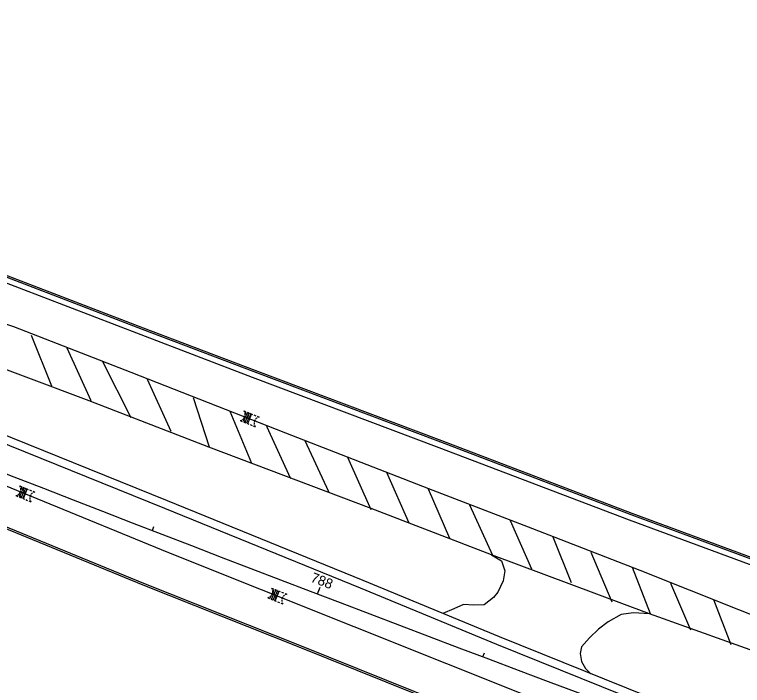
# Model space of a CAD drawing. Extents: x 2349621 to 2352073, y 625611 to 626553.
# Drawn here: x 2351167.3 to 2351373.1, y 625866.1 to 626055.7 of the extents above; entities that cross this region are included whole.
import ezdxf

# ---------------------------------------------------------------- set-up
doc = ezdxf.new("R2010")
doc.units = 0
for name, color, linetype in [('PM_X_Cells', 7, 'Continuous'), ('PM_X_Edge_Line', 7, 'Continuous'), ('PM_X_Lane_Line', 7, 'Continuous'), ('PV_X_Curb', 7, 'Continuous'), ('PV_X_EOP', 7, 'Continuous'), ('RW_X_CL', 7, 'Continuous'), ('RW_X_CL_100_Stations', 7, 'Continuous'), ('RW_X_CL_500_Stations', 7, 'Continuous')]:
    doc.layers.add(name, color=color, linetype=linetype)

msp = doc.modelspace()

# ---------------------------------------------------------------- linework, layer by layer
at = {"layer": 'PM_X_Cells'}
for p, q in [((2351232.19, 625943.66), (2351232.75, 625943.44)), ((2351233.62, 625941.02), (2351232.56, 625943.51)), ((2351233.13, 625943.29), (2351233.68, 625943.06)), ((2351233.87, 625941.65), (2351233.19, 625943.26)), ((2351233.24, 625940.08), (2351234.34, 625942.79)), ((2351234.13, 625942.28), (2351233.82, 625943)), ((2351234.06, 625942.91), (2351234.61, 625942.68)), ((2351231.09, 625940.95), (2351231.65, 625940.72)), ((2351231.66, 625940.72), (2351231.51, 625941.08)), ((2351232.29, 625940.46), (2351231.92, 625941.34)), ((2351232.92, 625940.21), (2351232.27, 625941.75)), ((2351233.36, 625940.39), (2351232.51, 625942.41)), ((2351233.79, 625941.44), (2351233.79, 625941.44)), ((2351234.99, 625942.53), (2351235.55, 625942.3)), ((2351235.92, 625942.15), (2351236.48, 625941.93)), ((2351232.02, 625940.57), (2351232.58, 625940.34)), ((2351232.96, 625940.19), (2351233.51, 625939.97)), ((2351233.89, 625939.81), (2351234.45, 625939.59)), ((2351234.82, 625939.44), (2351235.38, 625939.21)), ((2351168.78, 625922.47), (2351169.34, 625922.25)), ((2351170.2, 625919.83), (2351169.15, 625922.32)), ((2351169.71, 625922.09), (2351170.27, 625921.87)), ((2351170.46, 625920.46), (2351169.78, 625922.07)), ((2351168.88, 625919.27), (2351168.51, 625920.15)), ((2351169.5, 625919.02), (2351168.85, 625920.55)), ((2351169.95, 625919.2), (2351169.09, 625921.22)), ((2351169.82, 625918.89), (2351170.92, 625921.6)), ((2351170.37, 625920.24), (2351170.37, 625920.24)), ((2351170.71, 625921.09), (2351170.41, 625921.81)), ((2351170.64, 625921.72), (2351171.2, 625921.49)), ((2351171.58, 625921.34), (2351172.13, 625921.11)), ((2351172.51, 625920.96), (2351173.06, 625920.73)), ((2351167.68, 625919.76), (2351168.23, 625919.53)), ((2351168.25, 625919.53), (2351168.09, 625919.89)), ((2351168.61, 625919.38), (2351169.17, 625919.15)), ((2351169.54, 625919), (2351170.1, 625918.77)), ((2351170.48, 625918.62), (2351171.03, 625918.4)), ((2351171.41, 625918.24), (2351171.96, 625918.02)), ((2351239.98, 625893.59), (2351240.53, 625893.37)), ((2351241.4, 625890.95), (2351240.35, 625893.44)), ((2351240.08, 625890.39), (2351239.7, 625891.27)), ((2351240.7, 625890.14), (2351240.05, 625891.68)), ((2351241.15, 625890.32), (2351240.29, 625892.34)), ((2351240.91, 625893.21), (2351241.47, 625892.99)), ((2351241.66, 625891.58), (2351240.98, 625893.19)), ((2351241.02, 625890.01), (2351242.12, 625892.72)), ((2351241.57, 625891.37), (2351241.57, 625891.37)), ((2351241.91, 625892.21), (2351241.6, 625892.93)), ((2351241.84, 625892.84), (2351242.4, 625892.61)), ((2351242.78, 625892.46), (2351243.33, 625892.23)), ((2351243.71, 625892.08), (2351244.26, 625891.85)), ((2351238.88, 625890.88), (2351239.43, 625890.65)), ((2351239.44, 625890.65), (2351239.29, 625891.01)), ((2351239.81, 625890.5), (2351240.37, 625890.27)), ((2351240.74, 625890.12), (2351241.3, 625889.9)), ((2351241.67, 625889.74), (2351242.23, 625889.52)), ((2351242.61, 625889.37), (2351243.16, 625889.14))]:
    msp.add_line(p, q, dxfattribs=at)
for centre, start, end in [((2351230.8, 625942.65), 20.0075, 35.9489), ((2351230.8, 625942.65), 356.8106, 12.7435), ((2351230.8, 625942.65), 279.8966, 295.8433), ((2351230.8, 625942.65), 303.101, 319.0339), ((2351230.8, 625942.65), 326.3132, 349.543), ((2351236.78, 625940.22), 146.3043, 169.5319), ((2351236.78, 625940.22), 123.101, 139.0326), ((2351236.78, 625940.22), 99.8966, 115.8391), ((2351236.78, 625940.22), 176.81, 192.7435), ((2351236.78, 625940.22), 200.0045, 215.9489), ((2351167.38, 625921.46), 20.0075, 35.9489), ((2351167.38, 625921.46), 303.101, 319.0339), ((2351167.38, 625921.46), 326.3132, 349.543), ((2351167.38, 625921.46), 356.8106, 12.7435), ((2351173.36, 625919.03), 123.101, 139.0326), ((2351173.36, 625919.03), 99.8966, 115.8391), ((2351167.38, 625921.46), 279.8966, 295.8433), ((2351173.36, 625919.03), 176.81, 192.7435), ((2351173.36, 625919.03), 146.3043, 169.5319), ((2351173.36, 625919.03), 200.0045, 215.9489), ((2351238.58, 625892.58), 20.0075, 35.9489), ((2351238.58, 625892.58), 303.101, 319.0339), ((2351238.58, 625892.58), 326.3132, 349.543), ((2351238.58, 625892.58), 356.8106, 12.7435), ((2351244.56, 625890.15), 123.101, 139.0326), ((2351244.56, 625890.15), 99.8966, 115.8391), ((2351238.58, 625892.58), 279.8966, 295.8433), ((2351244.56, 625890.15), 176.81, 192.7435), ((2351244.56, 625890.15), 146.3043, 169.5319), ((2351244.56, 625890.15), 200.0045, 215.9489)]:
    msp.add_arc(centre, 1.73, start, end, dxfattribs=at)
at = {"layer": 'PM_X_Edge_Line'}
for p, q in [((2351172.03, 625965.11), (2351177.79, 625950.8)), ((2351182.14, 625961.52), (2351188.88, 625946.61)), ((2351192.14, 625957.67), (2351200.23, 625941.8)), ((2351204.82, 625952.63), (2351211.55, 625937.92)), ((2351217.78, 625947.48), (2351222.35, 625933.54)), ((2351228.16, 625943.59), (2351234.28, 625928.92)), ((2351238.52, 625939.38), (2351245.3, 625924.55)), ((2351249.35, 625935.3), (2351256.09, 625920.89)), ((2351261.46, 625930.59), (2351268.06, 625915.84)), ((2351272.42, 625926.35), (2351278.81, 625912.09)), ((2351284.23, 625921.66), (2351290.25, 625907.75)), ((2351295.9, 625917.13), (2351302.41, 625902.92)), ((2351307.39, 625912.68), (2351313.43, 625899.07)), ((2351319.45, 625908.09), (2351324.67, 625895.23)), ((2351330.26, 625903.71), (2351336.15, 625889.75)), ((2351341.94, 625899.49), (2351346.96, 625886.4)), ((2351352.79, 625894.98), (2351358.42, 625881.85)), ((2351364.94, 625890.36), (2351369.8, 625877.64))]:
    msp.add_line(p, q, dxfattribs=at)
for points in [[(2350977.47, 626053.74), (2351016.31, 626038.35), (2351064.02, 626019.46), (2351106.89, 626002.49), (2351147.94, 625986.36), (2351202.99, 625965.26), (2351234.48, 625953.25), (2351287.27, 625933.36), (2351341.06, 625912.89), (2351383.66, 625897.13), (2351431.5, 625879.43), (2351486.97, 625859.09), (2351534.91, 625841.93), (2351586.59, 625823.19), (2351648.67, 625801.11), (2351691.59, 625785.98), (2351744.85, 625767.54), (2351787.37, 625752.87), (2351845.28, 625733.19), (2351909.09, 625711.34), (2351976.75, 625688.75)], [(2350970.27, 626033.22), (2350999, 626021.78), (2351066.48, 625994.71), (2351080.71, 625988.99), (2351089.12, 625985.94), (2351098.37, 625983.24), (2351102.77, 625981.98), (2351110.19, 625980.37), (2351115.88, 625979.26), (2351128.77, 625976.9), (2351139.63, 625974.85), (2351148.96, 625972.97), (2351158.3, 625970.39), (2351167.01, 625967.53), (2351200.24, 625954.65), (2351243.91, 625937.45), (2351284.31, 625921.78), (2351313.78, 625910.44), (2351344.1, 625898.66), (2351385.94, 625881.99)], [(2350963.74, 626014.89), (2351032.32, 625987.17), (2351095.71, 625962.07), (2351152.54, 625939.23), (2351209.68, 625916.15), (2351265.03, 625893.7), (2351303.58, 625877.76), (2351345.44, 625860.89), (2351387.6, 625843.99), (2351430.99, 625827.11), (2351474.75, 625810.9), (2351502.4, 625801.12), (2351535.69, 625789.35), (2351577.68, 625775.6), (2351622.58, 625760.66), (2351663.85, 625747.4), (2351714.74, 625729.84), (2351764.19, 625714.28), (2351799.77, 625703.13), (2351848.31, 625686.82), (2351889.58, 625673.56), (2351936.76, 625658.21), (2351982.15, 625643.49)], [(2351976.42, 625623.21), (2351920.83, 625640.97), (2351841.95, 625666.41), (2351777.12, 625687.69), (2351724.25, 625705.24), (2351652.33, 625728.98), (2351591.84, 625748.83), (2351555.08, 625760.87), (2351507.03, 625777.09), (2351478.29, 625787.21), (2351423.53, 625807.58), (2351365.19, 625830.22), (2351304.85, 625854.49), (2351247.93, 625877.37), (2351203.89, 625894.92), (2351143.43, 625919.65), (2351117.74, 625929.97), (2351079.36, 625945.33), (2351042.9, 625960.12), (2351003.33, 625976.06), (2350965.81, 625991.28), (2350956.45, 625995.04)]]:
    msp.add_lwpolyline(points, dxfattribs=at)
at = {"layer": 'PM_X_Lane_Line'}
msp.add_lwpolyline([(2350960.41, 626005.5), (2351002.64, 625988.3), (2351066, 625962.88), (2351136.34, 625934.22), (2351210.8, 625903.65), (2351315.64, 625861.8), (2351357.25, 625845.01), (2351429.58, 625816.81), (2351493.91, 625793.24), (2351605.6, 625755.44), (2351685.16, 625729.5), (2351789.05, 625695.46), (2351865.04, 625671.13), (2351976.54, 625634.71)], dxfattribs=at)
at = {"layer": 'PV_X_Curb'}
msp.add_lwpolyline([(2350978.14, 626055.68), (2351017.07, 626040.25), (2351064.77, 626021.37), (2351107.64, 626004.39), (2351148.68, 625988.27), (2351203.72, 625967.18), (2351235.21, 625955.17), (2351288, 625935.28), (2351341.78, 625914.81), (2351384.37, 625899.05), (2351432.2, 625881.35), (2351487.67, 625861.02), (2351535.61, 625843.86), (2351587.29, 625825.12), (2351649.36, 625803.04), (2351692.27, 625787.92), (2351745.52, 625769.48), (2351788.03, 625754.81), (2351845.94, 625735.13), (2351909.74, 625713.28), (2351977.4, 625690.7)], dxfattribs=at)
at = {"layer": 'PV_X_EOP'}
for points in [[(2351977.24, 625690.22), (2351909.58, 625712.81), (2351845.78, 625734.65), (2351787.87, 625754.34), (2351745.36, 625769.01), (2351692.1, 625787.45), (2351649.19, 625802.57), (2351587.12, 625824.65), (2351535.44, 625843.39), (2351487.5, 625860.55), (2351432.03, 625880.88), (2351384.2, 625898.58), (2351341.6, 625914.34), (2351287.82, 625934.81), (2351235.03, 625954.7), (2351203.54, 625966.71), (2351148.5, 625987.81), (2351107.45, 626003.93), (2351064.59, 626020.91), (2351016.88, 626039.79), (2350977.96, 626055.22)], [(2351381.54, 625873.89), (2351346.84, 625886.35), (2351302.15, 625902.96), (2351268.11, 625916.06), (2351222.23, 625933.47), (2351188.42, 625946.53), (2351155.74, 625958.79), (2351100.22, 625980.56), (2351080.46, 625988.33), (2351066.22, 625994.04), (2350998.74, 626021.12), (2350970.01, 626032.55)], [(2351982.85, 625645.63), (2351937.46, 625660.36), (2351890.28, 625675.71), (2351849.01, 625688.96), (2351800.47, 625705.27), (2351764.87, 625716.44), (2351715.44, 625731.98), (2351664.57, 625749.54), (2351623.28, 625762.81), (2351578.39, 625777.74), (2351536.41, 625791.49), (2351503.15, 625803.24), (2351475.52, 625813.02), (2351431.79, 625829.22), (2351388.43, 625846.09), (2351346.28, 625862.98), (2351304.44, 625879.85), (2351265.89, 625895.79), (2351210.53, 625918.24), (2351153.38, 625941.32), (2351096.55, 625964.17), (2351033.16, 625989.26), (2350964.49, 626017.02)], [(2351976.27, 625622.73), (2351920.68, 625640.49), (2351841.8, 625665.93), (2351776.97, 625687.21), (2351724.09, 625704.77), (2351652.18, 625728.51), (2351591.68, 625748.36), (2351554.93, 625760.4), (2351506.86, 625776.62), (2351478.12, 625786.74), (2351423.35, 625807.11), (2351365, 625829.75), (2351304.66, 625854.02), (2351247.74, 625876.9), (2351203.71, 625894.46), (2351143.24, 625919.19), (2351117.55, 625929.5), (2351079.17, 625944.86), (2351042.71, 625959.65), (2351003.14, 625975.6), (2350965.62, 625990.82), (2350956.27, 625994.57)], [(2351302.15, 625902.96), (2351304.94, 625901.31), (2351305.94, 625898.45), (2351305.45, 625895.66), (2351303.98, 625892.46), (2351302.73, 625890.97), (2351300.08, 625888.89), (2351297.17, 625888.78), (2351294.19, 625888.94), (2351291.49, 625887.75), (2351288.43, 625886.42)], [(2351346.84, 625886.35), (2351342.32, 625886.59), (2351338.8, 625886.14), (2351335.15, 625884.05), (2351332.44, 625881.99), (2351329.82, 625879.55), (2351327.61, 625876.99), (2351327.22, 625875.16), (2351327.62, 625872.83), (2351328.7, 625870.88), (2351330.2, 625869.39)]]:
    msp.add_lwpolyline(points, dxfattribs=at)
at = {"layer": 'RW_X_CL'}
msp.add_arc((2356442.68, 639481.86), 14547.12, 247.922783, 252.452173, dxfattribs=at)
at = {"layer": 'RW_X_CL_100_Stations'}
for p, q in [((2351206.29, 625909.87), (2351206.72, 625910.99)), ((2351252.96, 625891.95), (2351253.68, 625893.82)), ((2351299.71, 625874.2), (2351300.13, 625875.32))]:
    msp.add_line(p, q, dxfattribs=at)
at = {"layer": 'RW_X_CL_500_Stations'}
msp.add_line((2351252.96, 625891.95), (2351253.39, 625893.08), dxfattribs=at)

# ---------------------------------------------------------------- texts
at = {"layer": 'RW_X_CL_100_Stations'}
msp.add_text('788', height=2.8, rotation=339.0991, dxfattribs=at).set_placement((2351250.81, 625895.5))

doc.saveas('drawing.dxf')
